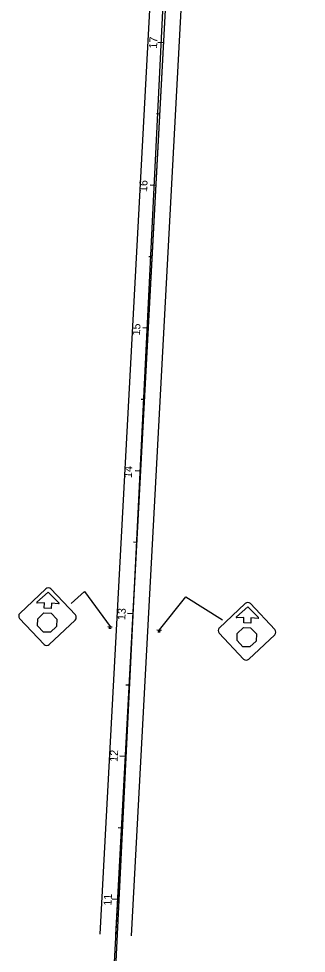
# Model space of a CAD drawing. Extents: x 1658454 to 1663955, y 480219 to 484109.
# Drawn here: x 1661276 to 1661478, y 481607 to 482260 of the extents above; entities that cross this region are included whole.
import ezdxf

# ---------------------------------------------------------------- set-up
doc = ezdxf.new("R2010")
doc.units = 0
for name, color, linetype in [('Default', 7, 'Continuous'), ('PM_P_CL_Double_Solid', 7, 'Continuous'), ('PV_P_EOP', 7, 'Continuous'), ('RW_X_CL_50', 7, 'Continuous'), ('SC_Scratch1', 7, 'Continuous'), ('SN_X_Public', 7, 'Continuous'), ('SV_X_CL_Survey_50', 7, 'Continuous'), ('SV_X_Text', 7, 'Continuous')]:
    doc.layers.add(name, color=color, linetype=linetype)

msp = doc.modelspace()

# ---------------------------------------------------------------- linework, layer by layer
at = {"layer": 'Default'}
for p, q in [((1661377.86, 482243.65), (1661373.87, 482243.87)), ((1661375.19, 482193.72), (1661372.79, 482193.85)), ((1661372.52, 482143.8), (1661368.52, 482144.01)), ((1661369.84, 482093.87), (1661367.45, 482094)), ((1661367.17, 482043.94), (1661363.18, 482044.15)), ((1661364.5, 481994.01), (1661362.1, 481994.14)), ((1661361.83, 481944.08), (1661357.83, 481944.3)), ((1661359.16, 481894.15), (1661356.76, 481894.28)), ((1661356.48, 481844.22), (1661352.49, 481844.44)), ((1661353.81, 481794.3), (1661351.42, 481794.42)), ((1661351.14, 481744.37), (1661347.15, 481744.58)), ((1661348.47, 481694.44), (1661346.07, 481694.57)), ((1661345.8, 481644.51), (1661341.8, 481644.72))]:
    msp.add_line(p, q, dxfattribs=at)
at = {"layer": 'PM_P_CL_Double_Solid'}
msp.add_line((1661344.46, 481619.54), (1661462.56, 483826.39), dxfattribs=at)
at = {"layer": 'PV_P_EOP'}
for p, q in [((1661333.48, 481620.13), (1661385.68, 482595.56)), ((1661355.44, 481618.95), (1661407.64, 482594.38))]:
    msp.add_line(p, q, dxfattribs=at)
at = {"layer": 'RW_X_CL_50'}
msp.add_line((1661341.73, 481544.59), (1661467.43, 484100.93), dxfattribs=at)
at = {"layer": 'SC_Scratch1'}
for p, q in [((1661289.15, 481852.32), (1661297.09, 481859.34)), ((1661297.09, 481859.34), (1661304.6, 481851.86)), ((1661294.37, 481851.92), (1661289.37, 481851.77)), ((1661294.26, 481848.17), (1661294.37, 481851.92)), ((1661299.25, 481848.02), (1661294.26, 481848.17)), ((1661299.37, 481851.77), (1661299.25, 481848.02)), ((1661304.35, 481851.33), (1661299.37, 481851.77)), ((1661428.75, 481842.07), (1661436.68, 481849.09)), ((1661436.68, 481849.09), (1661444.19, 481841.61)), ((1661289.6, 481835.77), (1661289.75, 481840.81)), ((1661289.75, 481840.81), (1661294.1, 481844.83)), ((1661294.1, 481844.83), (1661299.04, 481844.68)), ((1661299.04, 481844.68), (1661303.14, 481840.41)), ((1661303.14, 481840.41), (1661302.99, 481835.37)), ((1661433.96, 481841.67), (1661428.96, 481841.52)), ((1661433.85, 481837.92), (1661433.96, 481841.67)), ((1661438.96, 481841.52), (1661438.85, 481837.77)), ((1661443.94, 481841.08), (1661438.96, 481841.52)), ((1661293.7, 481831.5), (1661289.6, 481835.77)), ((1661302.99, 481835.37), (1661298.64, 481831.35)), ((1661429.34, 481830.56), (1661433.69, 481834.58)), ((1661433.69, 481834.58), (1661438.63, 481834.43)), ((1661438.85, 481837.77), (1661433.85, 481837.92)), ((1661438.63, 481834.43), (1661442.74, 481830.16)), ((1661298.64, 481831.35), (1661293.7, 481831.5)), ((1661429.19, 481825.52), (1661429.34, 481830.56)), ((1661442.74, 481830.16), (1661442.59, 481825.12)), ((1661433.29, 481821.25), (1661429.19, 481825.52)), ((1661438.24, 481821.1), (1661433.29, 481821.25)), ((1661442.59, 481825.12), (1661438.24, 481821.1))]:
    msp.add_line(p, q, dxfattribs=at)
for points in [[(1661277.2, 481844.58), (1661295.39, 481861.72)], [(1661298.92, 481861.62), (1661316.07, 481843.42)], [(1661313.04, 481851.44), (1661322.37, 481859.74), (1661340.34, 481835.34)], [(1661375, 481833.16), (1661393.3, 481856.21), (1661418.98, 481840.11)], [(1661416.79, 481834.32), (1661434.99, 481851.47)], [(1661438.52, 481851.37), (1661455.66, 481833.17)], [(1661294.24, 481822.85), (1661277.09, 481841.04)], [(1661315.97, 481839.89), (1661297.77, 481822.74)], [(1661433.83, 481812.6), (1661416.69, 481830.79)], [(1661455.56, 481829.64), (1661437.36, 481812.49)]]:
    msp.add_lwpolyline(points, dxfattribs=at)
for centre, radius, start, end in [((1661297.11, 481859.9), 2.5, 43.29934, 133.29934), ((1661289.36, 481852.09), 0.313, 131.50633, 271.69017), ((1661304.38, 481851.64), 0.313, 264.90851, 45.09235), ((1661436.7, 481849.65), 2.5, 43.29934, 133.29934), ((1661278.91, 481842.76), 2.5, 133.29934, 223.29934), ((1661314.25, 481841.71), 2.5, 313.29934, 43.29934), ((1661428.95, 481841.84), 0.313, 131.50633, 271.69017), ((1661443.97, 481841.39), 0.313, 264.90851, 45.09235), ((1661418.51, 481832.51), 2.5, 133.29934, 223.29934), ((1661453.84, 481831.46), 2.5, 313.29934, 43.29934), ((1661296.06, 481824.56), 2.5, 223.29934, 313.29934), ((1661435.65, 481814.31), 2.5, 223.29934, 313.29934)]:
    msp.add_arc(centre, radius, start, end, dxfattribs=at)
at = {"layer": 'SN_X_Public'}
for p, q in [((1661338.72, 481835.37), (1661341.92, 481835.19)), ((1661339.84, 481835.3), (1661339.75, 481833.71)), ((1661340.32, 481835.28), (1661340.32, 481835.28)), ((1661340.8, 481835.25), (1661340.71, 481833.65)), ((1661373.04, 481832.94), (1661376.24, 481832.76)), ((1661374.16, 481832.88), (1661374.07, 481831.28)), ((1661374.64, 481832.85), (1661374.64, 481832.85)), ((1661375.12, 481832.82), (1661375.03, 481831.22))]:
    msp.add_line(p, q, dxfattribs=at)
at = {"layer": 'SV_X_CL_Survey_50'}
msp.add_line((1661328.12, 481314.2), (1661477.68, 484108.99), dxfattribs=at)

# ---------------------------------------------------------------- texts
at = {"layer": 'SV_X_Text'}
for s, p in [('17', (1661373.17, 482239.37)), ('16', (1661366.21, 482139.12)), ('15', (1661361.25, 482038.82)), ('14', (1661355.58, 481939.18)), ('13', (1661350.99, 481839.74)), ('12', (1661345.61, 481740.62)), ('11', (1661341.27, 481640))]:
    msp.add_text(s, height=5.6, rotation=86.93677, dxfattribs=at).set_placement(p)

doc.saveas('drawing.dxf')
